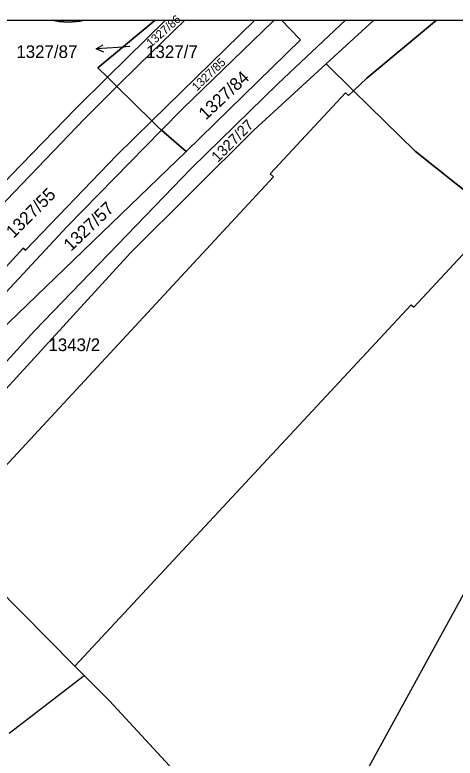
# Model space of a CAD drawing. Extents: x -598934 to -598196, y -1162208 to -1161502.
# Drawn here: x -598378.9 to -598319.6, y -1161604.5 to -1161504.5 of the extents above; entities that cross this region are included whole.
import ezdxf

# ---------------------------------------------------------------- set-up
doc = ezdxf.new("R2010")
doc.units = 0
for name, color, linetype in [('KN_CAR_KR', 7, 'Continuous'), ('KN_PARC_CIS_POM', 7, 'Continuous'), ('KN_PARC_CIS_POZ', 7, 'Continuous'), ('KN_PARC_PLOCHA', 7, 'Continuous'), ('PARC_C_SIPKA', 7, 'Continuous'), ('parcely_l', 7, 'Continuous')]:
    doc.layers.add(name, color=color, linetype=linetype)

msp = doc.modelspace()

# ---------------------------------------------------------------- linework, layer by layer
at = {"layer": 'KN_CAR_KR'}
for points in [[(-598325.19, -1161543.82), (-598315.06, -1161532.9)], [(-598370.8, -1161592.1), (-598325.55, -1161543.48)], [(-598325.55, -1161543.48), (-598325.19, -1161543.82)], [(-598341.18, -1161623.85), (-598303.83, -1161555.7)], [(-598379.65, -1161601.12), (-598369.55, -1161593.36)]]:
    msp.add_lwpolyline(points, dxfattribs=at)
at = {"layer": 'KN_PARC_PLOCHA'}
for points in [[(-598395.08, -1161567.59), (-598398.28, -1161564.31), (-598398.65, -1161564.03), (-598399.69, -1161562.98), (-598393.38, -1161556.09), (-598385.48, -1161547.59), (-598383.56, -1161549.55), (-598355.84, -1161522.87), (-598340.43, -1161507.82), (-598341.83, -1161506.38), (-598343.01, -1161505.18), (-598334.37, -1161505.18), (-598343.44, -1161513.72), (-598355.12, -1161525.1), (-598376.23, -1161546.99)], [(-598336.98, -1161511.07), (-598346.7, -1161519.98), (-598363.31, -1161536.51), (-598389.25, -1161564.81), (-598393.4, -1161569.31), (-598395.08, -1161567.59), (-598376.23, -1161546.99), (-598355.12, -1161525.1), (-598343.44, -1161513.72), (-598334.37, -1161505.18), (-598330.55, -1161505.18)], [(-598373.81, -1161505.18), (-598369.63, -1161505.18), (-598370.09, -1161505.31), (-598371.65, -1161505.47), (-598372.93, -1161505.37)], [(-598366.41, -1161512.86), (-598367.69, -1161511.6), (-598360, -1161505.18), (-598358.6, -1161505.18)], [(-598365.15, -1161514.1), (-598366.41, -1161512.86), (-598358.6, -1161505.18), (-598355.99, -1161505.18), (-598362.21, -1161511.17)], [(-598360.43, -1161518.74), (-598365.15, -1161514.1), (-598362.21, -1161511.17), (-598355.99, -1161505.18), (-598346.58, -1161505.18)], [(-598359.12, -1161519.98), (-598359.58, -1161519.58), (-598360.43, -1161518.74), (-598346.58, -1161505.18), (-598343.97, -1161505.18), (-598344.15, -1161505.35), (-598356.26, -1161517.07)], [(-598355.84, -1161522.87), (-598359.12, -1161519.98), (-598356.26, -1161517.07), (-598344.15, -1161505.35), (-598343.97, -1161505.18), (-598343.01, -1161505.18), (-598341.83, -1161506.38), (-598340.43, -1161507.82)], [(-598333.3, -1161514.67), (-598336.98, -1161511.07), (-598330.55, -1161505.18), (-598322.12, -1161505.18), (-598331.51, -1161512.97)], [(-598258.37, -1161526.97), (-598260.89, -1161529.57), (-598263.39, -1161532.94), (-598262.19, -1161534.05), (-598267.45, -1161540.35), (-598269.13, -1161543.42), (-598268.44, -1161544.09), (-598270.88, -1161548.57), (-598270.76, -1161548.66), (-598277.75, -1161561.08), (-598291.69, -1161549.87), (-598303.99, -1161539.63), (-598316.62, -1161529.5), (-598325, -1161522.8), (-598333.3, -1161514.67), (-598331.51, -1161512.97), (-598322.12, -1161505.18), (-598281.71, -1161505.18), (-598274.21, -1161512.18), (-598265.85, -1161519.99)], [(-598333.3, -1161514.67), (-598333.97, -1161515.3), (-598334.36, -1161514.94), (-598344.5, -1161525.85), (-598344.06, -1161526.26), (-598383.11, -1161568.33), (-598383.48, -1161567.99), (-598388.28, -1161573.14), (-598387.95, -1161573.46), (-598388.6, -1161574.13), (-598393.4, -1161569.31), (-598389.25, -1161564.81), (-598363.31, -1161536.51), (-598346.7, -1161519.98), (-598336.98, -1161511.07)], [(-598365.15, -1161514.1), (-598369.49, -1161518.44), (-598382.18, -1161531.62), (-598381.89, -1161531.93), (-598391.04, -1161541.89), (-598392.66, -1161540.24), (-598390.71, -1161538.12), (-598379.41, -1161526.08), (-598370.77, -1161517.14), (-598366.41, -1161512.86)], [(-598360.43, -1161518.74), (-598365.18, -1161523.39), (-598377.43, -1161536.14), (-598377.75, -1161535.87), (-598387.04, -1161545.99), (-598391.04, -1161541.89), (-598381.89, -1161531.93), (-598382.18, -1161531.62), (-598369.49, -1161518.44), (-598365.15, -1161514.1)], [(-598277.75, -1161561.08), (-598281.57, -1161567.88), (-598322.97, -1161643.5), (-598335.08, -1161630.46), (-598341.18, -1161623.85), (-598341.89, -1161623.08), (-598366.15, -1161596.79), (-598369.55, -1161593.36), (-598370.8, -1161592.1), (-598388.6, -1161574.13), (-598387.95, -1161573.46), (-598388.28, -1161573.14), (-598383.48, -1161567.99), (-598383.11, -1161568.33), (-598344.06, -1161526.26), (-598344.5, -1161525.85), (-598334.36, -1161514.94), (-598333.97, -1161515.3), (-598333.3, -1161514.67), (-598325, -1161522.8), (-598316.62, -1161529.5), (-598303.99, -1161539.63), (-598291.69, -1161549.87)], [(-598359.12, -1161519.98), (-598371.85, -1161532.94), (-598385.48, -1161547.59), (-598387.04, -1161545.99), (-598377.75, -1161535.87), (-598377.43, -1161536.14), (-598365.18, -1161523.39), (-598360.43, -1161518.74), (-598359.58, -1161519.58)], [(-598355.84, -1161522.87), (-598383.56, -1161549.55), (-598385.48, -1161547.59), (-598371.85, -1161532.94), (-598359.12, -1161519.98)], [(-598335.08, -1161630.46), (-598323.26, -1161644.05), (-598334.82, -1161665.7), (-598338.44, -1161661.36), (-598341.1, -1161658.12), (-598350.93, -1161646.15), (-598351.03, -1161646.03), (-598365.81, -1161628.03), (-598385.4, -1161607.3), (-598388.18, -1161604.36), (-598396.66, -1161595.57), (-598402.81, -1161589.15), (-598388.6, -1161574.13), (-598370.8, -1161592.1), (-598369.55, -1161593.36), (-598366.15, -1161596.79), (-598341.89, -1161623.08), (-598341.18, -1161623.85)]]:
    msp.add_lwpolyline(points, close=True, dxfattribs=at)
msp.add_lwpolyline([(-598398.32, -1161505.18), (-598373.81, -1161505.18), (-598372.93, -1161505.37), (-598371.65, -1161505.47), (-598370.09, -1161505.31), (-598369.63, -1161505.18), (-598360, -1161505.18), (-598367.69, -1161511.6), (-598366.41, -1161512.86), (-598370.77, -1161517.14), (-598379.41, -1161526.08)], dxfattribs=at)
at = {"layer": 'PARC_C_SIPKA'}
for points in [[(-598366.92, -1161509.49), (-598367.95, -1161509.06), (-598366.99, -1161508.49)], [(-598363.41, -1161508.74), (-598364.96, -1161508.85), (-598367.95, -1161509.06)]]:
    msp.add_lwpolyline(points, dxfattribs=at)
at = {"layer": 'parcely_l'}
for points in [[(-598398.32, -1161505.18), (-598373.81, -1161505.18)], [(-598334.37, -1161505.18), (-598343.44, -1161513.72), (-598355.12, -1161525.1), (-598376.23, -1161546.99), (-598395.08, -1161567.59)], [(-598373.81, -1161505.18), (-598369.63, -1161505.18)], [(-598369.63, -1161505.18), (-598370.09, -1161505.31), (-598371.65, -1161505.47), (-598372.93, -1161505.37), (-598373.81, -1161505.18)], [(-598369.63, -1161505.18), (-598360, -1161505.18)], [(-598360, -1161505.18), (-598367.69, -1161511.6), (-598366.41, -1161512.86)], [(-598366.41, -1161512.86), (-598358.6, -1161505.18)], [(-598355.99, -1161505.18), (-598362.21, -1161511.17), (-598365.15, -1161514.1)], [(-598360.43, -1161518.74), (-598346.58, -1161505.18)], [(-598360, -1161505.18), (-598358.6, -1161505.18)], [(-598343.97, -1161505.18), (-598344.15, -1161505.35), (-598356.26, -1161517.07), (-598359.12, -1161519.98)], [(-598358.6, -1161505.18), (-598355.99, -1161505.18)], [(-598355.99, -1161505.18), (-598346.58, -1161505.18)], [(-598355.84, -1161522.87), (-598340.43, -1161507.82), (-598341.83, -1161506.38), (-598343.01, -1161505.18)], [(-598346.58, -1161505.18), (-598343.97, -1161505.18)], [(-598343.97, -1161505.18), (-598343.01, -1161505.18)], [(-598343.01, -1161505.18), (-598334.37, -1161505.18)], [(-598336.98, -1161511.07), (-598330.55, -1161505.18)], [(-598334.37, -1161505.18), (-598330.55, -1161505.18)], [(-598322.12, -1161505.18), (-598331.51, -1161512.97), (-598333.3, -1161514.67)], [(-598330.55, -1161505.18), (-598322.12, -1161505.18)], [(-598322.12, -1161505.18), (-598281.71, -1161505.18)], [(-598393.4, -1161569.31), (-598389.25, -1161564.81), (-598363.31, -1161536.51), (-598346.7, -1161519.98), (-598336.98, -1161511.07)], [(-598336.98, -1161511.07), (-598333.3, -1161514.67)], [(-598366.41, -1161512.86), (-598370.77, -1161517.14), (-598379.41, -1161526.08), (-598390.71, -1161538.12), (-598392.66, -1161540.24)], [(-598365.15, -1161514.1), (-598366.41, -1161512.86)], [(-598391.04, -1161541.89), (-598381.89, -1161531.93), (-598382.18, -1161531.62), (-598369.49, -1161518.44), (-598365.15, -1161514.1)], [(-598365.15, -1161514.1), (-598360.43, -1161518.74)], [(-598333.3, -1161514.67), (-598333.97, -1161515.3), (-598334.36, -1161514.94), (-598344.5, -1161525.85), (-598344.06, -1161526.26), (-598383.11, -1161568.33), (-598383.48, -1161567.99), (-598388.28, -1161573.14), (-598387.95, -1161573.46), (-598388.6, -1161574.13)], [(-598277.75, -1161561.08), (-598291.69, -1161549.87), (-598303.99, -1161539.63), (-598316.62, -1161529.5), (-598325, -1161522.8), (-598333.3, -1161514.67)], [(-598387.04, -1161545.99), (-598377.75, -1161535.87), (-598377.43, -1161536.14), (-598365.18, -1161523.39), (-598360.43, -1161518.74)], [(-598360.43, -1161518.74), (-598359.58, -1161519.58), (-598359.12, -1161519.98)], [(-598359.12, -1161519.98), (-598371.85, -1161532.94), (-598385.48, -1161547.59)], [(-598359.12, -1161519.98), (-598355.84, -1161522.87)], [(-598355.84, -1161522.87), (-598383.56, -1161549.55), (-598385.48, -1161547.59)], [(-598388.6, -1161574.13), (-598370.8, -1161592.1), (-598369.55, -1161593.36), (-598366.15, -1161596.79), (-598341.89, -1161623.08), (-598341.18, -1161623.85), (-598335.08, -1161630.46)]]:
    msp.add_lwpolyline(points, dxfattribs=at)

# ---------------------------------------------------------------- texts
at = {"layer": 'KN_PARC_CIS_POM'}
msp.add_text('1327/87', height=0.1, dxfattribs=at).set_placement((-598363.74, -1161508.74))
at = {"layer": 'KN_PARC_CIS_POZ'}
for s, height, rotation, p in [('1327/86', 1.14, 41.5757, (-598360.56, -1161508.88)), ('1327/85', 1.14, 43.7245, (-598354.39, -1161514.78)), ('1327/84', 1.7, 43.0454, (-598353.18, -1161518.7)), ('1327/27', 1.45, 45.0224, (-598351.56, -1161524.38)), ('1327/55', 1.7, 45.0177, (-598379.05, -1161534.61)), ('1327/57', 1.7, 43.6953, (-598371.34, -1161536.38))]:
    msp.add_text(s, height=height, rotation=rotation, dxfattribs=at).set_placement(p)
for s, p in [('1327/87', (-598378.68, -1161510.27)), ('1327/7', (-598361.21, -1161510.28)), ('1343/2', (-598374.36, -1161549.71))]:
    msp.add_text(s, height=1.7, dxfattribs=at).set_placement(p)

doc.saveas('drawing.dxf')
